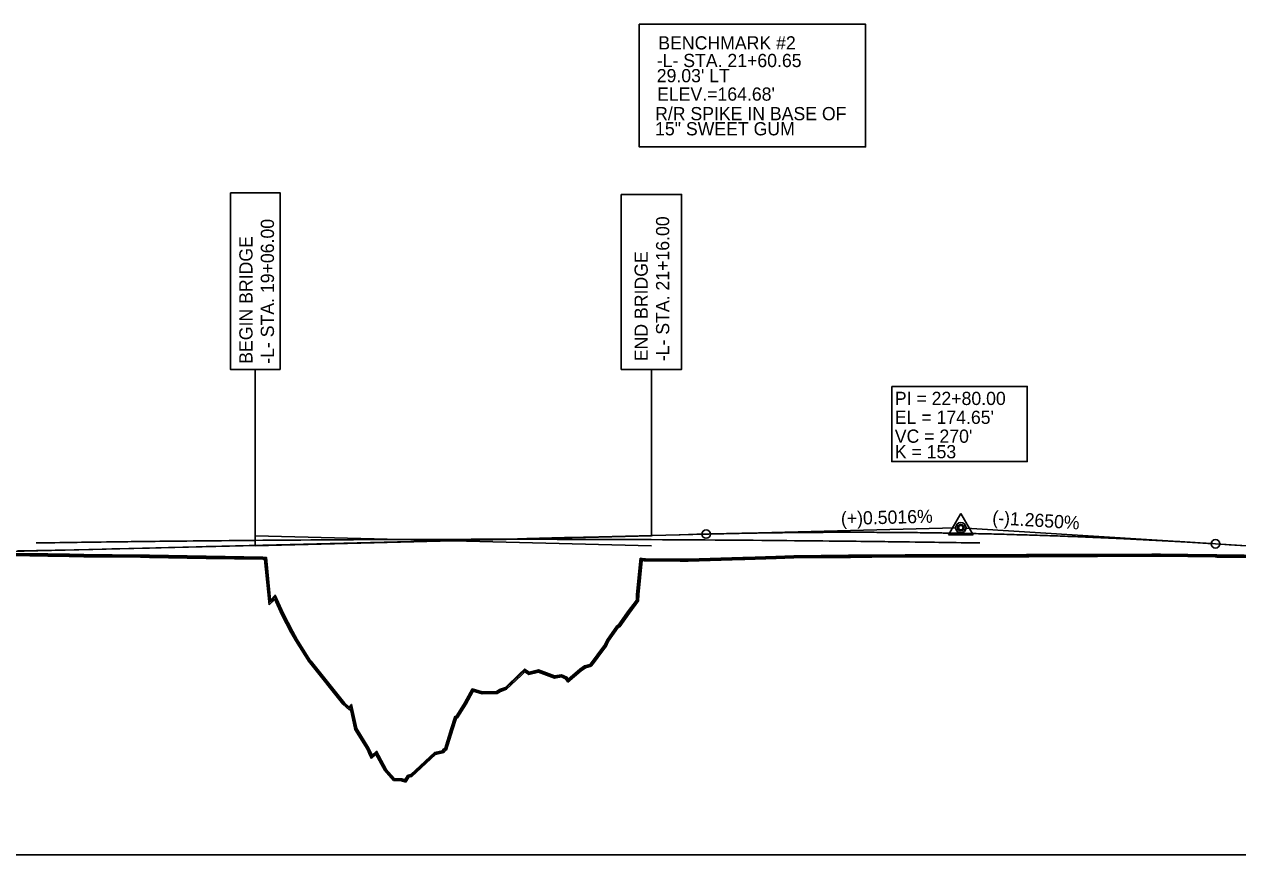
# Model space of a CAD drawing. Extents: x 2321227 to 2323611, y 920570 to 921870.
# Drawn here: x 2322011 to 2322654, y 920570 to 921010 of the extents above; entities that cross this region are included whole.
import ezdxf

# ---------------------------------------------------------------- set-up
doc = ezdxf.new("R2010")
doc.units = 0
for name, color, linetype in [('Exist Profile Cell', 7, 'Continuous'), ('Exist Vertical Profile Ground Line', 7, 'Continuous'), ('Prop Grid Mask', 7, 'Continuous'), ('Prop PFL Text', 7, 'Continuous'), ('Prop PFL VPI Symbol CELL', 7, 'Continuous'), ('Prop Vertical Profile Curve Label', 7, 'Continuous'), ('Prop Vertical Profile Grade', 7, 'Continuous'), ('Prop Vertical Profile Grade Label', 7, 'Continuous'), ('Prop VPI Label', 7, 'Continuous'), ('Scratch_Level_0', 7, 'Continuous'), ('Scratch_Level_1', 7, 'Continuous'), ('Scratch_Level_2', 7, 'Continuous'), ('Scratch_Level_3', 7, 'Continuous'), ('Scratch_Level_5', 7, 'Continuous')]:
    doc.layers.add(name, color=color, linetype=linetype)

# ---------------------------------------------------------------- blocks, each defined once
blk = doc.blocks.new('Profile VPI Symbol')
at = {"layer": 'Prop PFL VPI Symbol CELL'}
for p, q in [((-0.001, 0.147), (-0.13, -0.077)), ((-0.001, 0.147), (0.129, -0.077)), ((-0.13, -0.077), (0.129, -0.077))]:
    blk.add_line(p, q, dxfattribs=at)
for radius in [0.035, 0.024]:
    blk.add_circle((-0.001, -0.003), radius, dxfattribs=at)

msp = doc.modelspace()

# ---------------------------------------------------------------- linework, layer by layer
at = {"layer": 'Exist Profile Cell'}
msp.add_line((2321226.97, 920570.07), (2323610.74, 920570.07), dxfattribs=at)
at = {"layer": 'Exist Vertical Profile Ground Line'}
for p, q in [((2322003.77, 920728.54), (2322022.98, 920728.33)), ((2322022.98, 920728.33), (2322033.77, 920728.21)), ((2322033.77, 920728.21), (2322034.12, 920728.23)), ((2322034.12, 920728.23), (2322034.57, 920728.02)), ((2322034.57, 920728.02), (2322042.1, 920727.95)), ((2322042.1, 920727.95), (2322072.1, 920727.7)), ((2322512.97, 920727.93), (2322541.79, 920727.96)), ((2322541.79, 920727.96), (2322542.99, 920727.97)), ((2322542.99, 920727.97), (2322549, 920727.98)), ((2322549, 920727.98), (2322549.41, 920727.98)), ((2322549.41, 920727.98), (2322561.55, 920728.02)), ((2322561.55, 920728.02), (2322578.22, 920728.08)), ((2322578.22, 920728.08), (2322579.39, 920728.08)), ((2322579.39, 920728.08), (2322608.29, 920728.19)), ((2322608.29, 920728.19), (2322609.37, 920728.19)), ((2322609.37, 920728.19), (2322612.4, 920728.2)), ((2322612.4, 920728.2), (2322612.79, 920728.2)), ((2322612.79, 920728.2), (2322641.81, 920727.82)), ((2322072.1, 920727.7), (2322076.92, 920727.61)), ((2322076.92, 920727.61), (2322106.93, 920727.09)), ((2322106.93, 920727.09), (2322136.96, 920726.57)), ((2322136.96, 920726.57), (2322137.87, 920726.54)), ((2322137.87, 920726.54), (2322140.31, 920702.47)), ((2322336.24, 920707.89), (2322338.03, 920725.88)), ((2322338.03, 920725.88), (2322339.15, 920725.74)), ((2322339.15, 920725.74), (2322339.83, 920725.74)), ((2322339.83, 920725.74), (2322358.16, 920725.55)), ((2322358.16, 920725.55), (2322361.73, 920725.52)), ((2322361.73, 920725.52), (2322362.42, 920725.55)), ((2322362.42, 920725.55), (2322391.54, 920726.48)), ((2322391.54, 920726.48), (2322392.5, 920726.52)), ((2322392.5, 920726.52), (2322409.01, 920727.05)), ((2322409.01, 920727.05), (2322418.43, 920727.35)), ((2322418.43, 920727.35), (2322447.47, 920727.59)), ((2322447.47, 920727.59), (2322448.41, 920727.6)), ((2322448.41, 920727.6), (2322459.86, 920727.69)), ((2322459.86, 920727.69), (2322477.56, 920727.84)), ((2322477.56, 920727.84), (2322478.39, 920727.85)), ((2322478.39, 920727.85), (2322482.95, 920727.89)), ((2322482.95, 920727.89), (2322510.7, 920727.91)), ((2322510.7, 920727.91), (2322511.96, 920727.92)), ((2322511.96, 920727.92), (2322512.97, 920727.93)), ((2322641.81, 920727.82), (2322642.71, 920727.79)), ((2322642.71, 920727.79), (2322663.25, 920727.52)), ((2322140.31, 920702.47), (2322141.87, 920704.12)), ((2322141.87, 920704.12), (2322143.21, 920705.63)), ((2322143.21, 920705.63), (2322146.99, 920697.31)), ((2322331.27, 920698.07), (2322336.14, 920704.63)), ((2322336.14, 920704.63), (2322336.24, 920707.89)), ((2322146.99, 920697.31), (2322151.91, 920687.84)), ((2322326.15, 920690.77), (2322331.27, 920698.07)), ((2322320.31, 920683.21), (2322325.37, 920690.43)), ((2322325.37, 920690.43), (2322326.15, 920690.77)), ((2322151.91, 920687.84), (2322154.24, 920683.56)), ((2322154.24, 920683.56), (2322161.52, 920672)), ((2322318.92, 920680.3), (2322320.31, 920683.21)), ((2322312.08, 920671.18), (2322317.63, 920678.64)), ((2322317.63, 920678.64), (2322318.92, 920680.3)), ((2322161.52, 920672), (2322161.91, 920671.78)), ((2322161.91, 920671.78), (2322179.5, 920649.78)), ((2322311.01, 920669.91), (2322312.08, 920671.18)), ((2322266.19, 920657.73), (2322273.89, 920665.03)), ((2322273.89, 920665.03), (2322275.9, 920667.03)), ((2322275.9, 920667.03), (2322278.04, 920665.51)), ((2322278.04, 920665.51), (2322283.09, 920666.81)), ((2322283.09, 920666.81), (2322291.59, 920663.62)), ((2322291.59, 920663.62), (2322295.24, 920664.3)), ((2322295.24, 920664.3), (2322297.44, 920663.24)), ((2322298.73, 920661.54), (2322305.78, 920667.44)), ((2322305.78, 920667.44), (2322307.99, 920669.14)), ((2322307.99, 920669.14), (2322311.01, 920669.91)), ((2322262.91, 920656.62), (2322266.19, 920657.73)), ((2322297.44, 920663.24), (2322298.73, 920661.54)), ((2322244.83, 920649.91), (2322248.57, 920656.64)), ((2322248.57, 920656.64), (2322253.21, 920655.25)), ((2322253.21, 920655.25), (2322261.22, 920655.53)), ((2322261.22, 920655.53), (2322262.91, 920656.62)), ((2322179.5, 920649.78), (2322182.96, 920646.58)), ((2322182.96, 920646.58), (2322183.47, 920647.21)), ((2322183.47, 920647.21), (2322185.77, 920636.48)), ((2322240.12, 920642.52), (2322244.83, 920649.91)), ((2322237.78, 920636.5), (2322239.65, 920642.42)), ((2322239.65, 920642.42), (2322240.12, 920642.52)), ((2322185.77, 920636.48), (2322192.29, 920626.04)), ((2322234.31, 920625.66), (2322237.78, 920636.5)), ((2322192.29, 920626.04), (2322193.77, 920622.59)), ((2322232.88, 920624.21), (2322233.43, 920625.18)), ((2322233.43, 920625.18), (2322234.31, 920625.66)), ((2322193.77, 920622.59), (2322194.69, 920621.12)), ((2322194.69, 920621.12), (2322196.97, 920623.11)), ((2322196.97, 920623.11), (2322201.41, 920614.81)), ((2322216.06, 920611.5), (2322228.56, 920623.17)), ((2322228.56, 920623.17), (2322232.88, 920624.21)), ((2322201.41, 920614.81), (2322206.31, 920609.37)), ((2322206.31, 920609.37), (2322210.53, 920609.16)), ((2322210.53, 920609.16), (2322212.79, 920608.51)), ((2322212.79, 920608.51), (2322214.44, 920611.14)), ((2322214.44, 920611.14), (2322216.06, 920611.5))]:
    msp.add_line(p, q, dxfattribs=at)
at = {"layer": 'Prop Grid Mask'}
for points in [[(2322336.52, 921010.03), (2322456.52, 921010.03), (2322456.52, 920945.03), (2322336.52, 920945.03)], [(2322119.82, 920920.74), (2322146.12, 920920.74), (2322146.12, 920827.2), (2322119.82, 920827.2)], [(2322326.96, 920919.86), (2322358.98, 920919.86), (2322358.98, 920827.2), (2322326.96, 920827.2)], [(2322470.38, 920818.15), (2322542.17, 920818.15), (2322542.17, 920778.32), (2322470.38, 920778.32)]]:
    msp.add_lwpolyline(points, close=True, dxfattribs=at)
at = {"layer": 'Prop Vertical Profile Curve Label'}
for p, q in [((2322132.97, 920733.94), (2322132.97, 920827.2)), ((2322342.97, 920739.21), (2322342.97, 920827.2))]:
    msp.add_line(p, q, dxfattribs=at)
for centre in [(2322371.97, 920739.94), (2322641.97, 920734.79)]:
    msp.add_circle(centre, 2.25, dxfattribs=at)
at = {"layer": 'Prop Vertical Profile Grade'}
for p, q in [((2322001.97, 920730.66), (2322371.97, 920739.94)), ((2322641.97, 920734.79), (2322666.97, 920733.2))]:
    msp.add_line(p, q, dxfattribs=at)
msp.add_spline([(2322371.97, 920739.94), (2322377.37, 920740.07), (2322382.77, 920740.19), (2322388.17, 920740.3), (2322393.57, 920740.4), (2322398.97, 920740.5), (2322404.37, 920740.58), (2322409.77, 920740.65), (2322415.17, 920740.72), (2322420.57, 920740.77), (2322425.97, 920740.82), (2322431.37, 920740.85), (2322436.77, 920740.88), (2322442.17, 920740.89), (2322447.57, 920740.9), (2322452.97, 920740.9), (2322458.37, 920740.88), (2322463.77, 920740.86), (2322469.17, 920740.83), (2322474.57, 920740.79), (2322479.97, 920740.74), (2322485.37, 920740.68), (2322490.77, 920740.61), (2322496.17, 920740.53), (2322501.57, 920740.44), (2322506.97, 920740.34), (2322512.37, 920740.24), (2322517.77, 920740.12), (2322523.17, 920739.99), (2322528.57, 920739.85), (2322533.97, 920739.71), (2322539.37, 920739.55), (2322544.77, 920739.39), (2322550.17, 920739.21), (2322555.57, 920739.03), (2322560.97, 920738.84), (2322566.37, 920738.63), (2322571.77, 920738.42), (2322577.17, 920738.2), (2322582.57, 920737.97), (2322587.97, 920737.72), (2322593.37, 920737.47), (2322598.77, 920737.21), (2322604.17, 920736.94), (2322609.57, 920736.66), (2322614.97, 920736.37), (2322620.37, 920736.08), (2322625.77, 920735.77), (2322631.17, 920735.45), (2322636.57, 920735.12), (2322641.97, 920734.79)], degree=3, dxfattribs=at)
at = {"layer": 'Prop VPI Label'}
for p, q in [((2322371.97, 920739.94), (2322504.22, 920743.26)), ((2322641.97, 920734.79), (2322509.72, 920743.15))]:
    msp.add_line(p, q, dxfattribs=at)
msp.add_circle((2322506.97, 920743.32), 2.75, dxfattribs=at)
at = {"layer": 'Scratch_Level_0'}
msp.add_open_spline([(2322016.91, 920735.23), (2322027.32, 920735.39), (2322037.74, 920735.54), (2322058.58, 920735.82), (2322089.84, 920736.21), (2322162.77, 920736.91), (2322266.97, 920737.31), (2322371.17, 920736.91), (2322444.1, 920736.21), (2322475.36, 920735.82), (2322496.2, 920735.54), (2322506.62, 920735.39), (2322517.03, 920735.23)], degree=3, dxfattribs=at)
at = {"layer": 'Scratch_Level_1'}
for p, q in [((2322132.97, 920738.97), (2322342.97, 920733.72)), ((2322342.97, 920738.97), (2322132.97, 920733.72))]:
    msp.add_line(p, q, dxfattribs=at)
for points in [[(2321985.27, 920729.85), (2322023, 920729.43), (2322033.74, 920729.31), (2322034.33, 920729.35), (2322034.82, 920729.12), (2322042.11, 920729.05), (2322072.11, 920728.8), (2322076.94, 920728.71), (2322106.95, 920728.19), (2322136.99, 920727.67), (2322138.87, 920727.6), (2322141.16, 920704.98), (2322143.51, 920707.62), (2322147.98, 920697.79), (2322152.88, 920688.36), (2322155.19, 920684.12), (2322162.29, 920672.83), (2322162.63, 920672.64), (2322180.31, 920650.53), (2322182.85, 920648.18), (2322184.06, 920649.68), (2322186.81, 920636.9), (2322193.27, 920626.55), (2322194.75, 920623.1), (2322194.94, 920622.8), (2322197.28, 920624.85), (2322202.32, 920615.45), (2322206.82, 920610.45), (2322210.71, 920610.26), (2322212.3, 920609.8), (2322213.75, 920612.11), (2322215.53, 920612.51), (2322228.02, 920624.17), (2322232.16, 920625.17), (2322232.62, 920625.99), (2322233.4, 920626.42), (2322236.73, 920636.83), (2322238.8, 920643.37), (2322239.45, 920643.5), (2322243.89, 920650.48), (2322248.04, 920657.95), (2322253.35, 920656.36), (2322260.88, 920656.62), (2322262.43, 920657.62), (2322265.61, 920658.7), (2322273.12, 920665.82), (2322275.78, 920668.46), (2322278.26, 920666.71), (2322283.16, 920667.96), (2322291.69, 920664.76), (2322295.39, 920665.45), (2322298.15, 920664.11), (2322298.91, 920663.12), (2322305.09, 920668.29), (2322307.5, 920670.15), (2322310.39, 920670.89), (2322311.22, 920671.87), (2322316.76, 920679.31), (2322317.98, 920680.88), (2322319.36, 920683.77), (2322324.65, 920691.32), (2322325.43, 920691.66), (2322330.38, 920698.72), (2322335.05, 920705.01), (2322335.15, 920707.96), (2322337.05, 920727.12), (2322339.22, 920726.84), (2322339.83, 920726.84), (2322358.18, 920726.65), (2322361.71, 920726.62), (2322362.38, 920726.65), (2322391.5, 920727.58), (2322392.46, 920727.62), (2322408.98, 920728.15), (2322418.41, 920728.45), (2322447.46, 920728.69), (2322448.4, 920728.7), (2322477.55, 920728.94), (2322478.37, 920728.95), (2322482.95, 920728.99), (2322511.96, 920729.02), (2322512.97, 920729.03), (2322541.78, 920729.06), (2322542.98, 920729.07), (2322549, 920729.08), (2322549.4, 920729.08), (2322578.22, 920729.18), (2322579.38, 920729.18), (2322608.29, 920729.29), (2322609.37, 920729.29), (2322612.79, 920729.3), (2322641.83, 920728.92), (2322642.74, 920728.89), (2322671.88, 920728.51)], [(2321985.27, 920729.37), (2322022.99, 920728.96), (2322033.76, 920728.83), (2322034.24, 920728.87), (2322034.71, 920728.64), (2322042.11, 920728.57), (2322072.11, 920728.32), (2322076.93, 920728.24), (2322106.94, 920727.72), (2322136.98, 920727.2), (2322138.44, 920727.14), (2322140.8, 920703.9), (2322141.41, 920704.55), (2322143.38, 920706.76), (2322147.55, 920697.58), (2322152.47, 920688.14), (2322154.78, 920683.88), (2322161.96, 920672.47), (2322162.32, 920672.27), (2322179.96, 920650.21), (2322182.89, 920647.49), (2322183.81, 920648.61), (2322186.36, 920636.72), (2322192.84, 920626.33), (2322194.33, 920622.88), (2322194.83, 920622.08), (2322197.15, 920624.1), (2322201.93, 920615.17), (2322206.6, 920609.99), (2322210.64, 920609.78), (2322212.51, 920609.24), (2322214.05, 920611.69), (2322215.76, 920612.08), (2322228.25, 920623.74), (2322232.47, 920624.76), (2322232.97, 920625.64), (2322233.79, 920626.09), (2322237.18, 920636.69), (2322239.17, 920642.96), (2322239.74, 920643.08), (2322244.29, 920650.23), (2322248.27, 920657.38), (2322253.29, 920655.88), (2322261.02, 920656.15), (2322262.64, 920657.19), (2322265.86, 920658.28), (2322273.45, 920665.48), (2322275.83, 920667.84), (2322278.17, 920666.19), (2322283.13, 920667.46), (2322291.65, 920664.27), (2322295.32, 920664.95), (2322297.85, 920663.74), (2322298.83, 920662.44), (2322305.39, 920667.92), (2322307.71, 920669.71), (2322310.66, 920670.47), (2322311.59, 920671.57), (2322317.14, 920679.02), (2322318.39, 920680.63), (2322319.77, 920683.53), (2322324.96, 920690.94), (2322325.74, 920691.27), (2322330.76, 920698.44), (2322335.52, 920704.84), (2322335.62, 920707.93), (2322337.48, 920726.59), (2322339.19, 920726.36), (2322339.83, 920726.36), (2322358.17, 920726.18), (2322361.72, 920726.14), (2322362.4, 920726.17), (2322391.51, 920727.11), (2322392.48, 920727.14), (2322408.99, 920727.68), (2322418.42, 920727.97), (2322447.47, 920728.21), (2322448.41, 920728.23), (2322477.56, 920728.46), (2322478.38, 920728.47), (2322482.95, 920728.51), (2322511.96, 920728.54), (2322512.97, 920728.55), (2322541.78, 920728.58), (2322542.99, 920728.59), (2322549, 920728.6), (2322549.4, 920728.6), (2322578.22, 920728.7), (2322579.39, 920728.71), (2322608.29, 920728.81), (2322609.37, 920728.81), (2322612.79, 920728.82), (2322641.82, 920728.44), (2322642.73, 920728.41), (2322671.87, 920728.03)]]:
    msp.add_lwpolyline(points, dxfattribs=at)
at = {"layer": 'Scratch_Level_2'}
msp.add_lwpolyline([(2322006.97, 920731), (2322016.97, 920731.2), (2322026.97, 920731.42), (2322036.97, 920731.63), (2322046.97, 920731.86), (2322056.97, 920732.08), (2322066.97, 920732.32), (2322076.97, 920732.56), (2322086.97, 920732.8), (2322096.97, 920733.05), (2322102.96, 920733.2), (2322102.97, 920733.2), (2322106.97, 920733.3), (2322107.97, 920733.33), (2322136.97, 920734.06), (2322146.97, 920734.31), (2322166.97, 920734.81), (2322186.97, 920735.31), (2322216.97, 920736.06), (2322236.97, 920736.56), (2322256.97, 920737.06), (2322266.97, 920737.31), (2322276.97, 920737.56), (2322296.97, 920738.06), (2322316.97, 920738.56), (2322342.97, 920739.22), (2322357.97, 920739.59), (2322358.16, 920739.6), (2322366.97, 920739.82), (2322367.97, 920739.84), (2322372.96, 920739.97), (2322372.97, 920739.97), (2322372.98, 920739.97), (2322373.97, 920739.99), (2322374.97, 920740.02), (2322376.97, 920740.06), (2322386.97, 920740.28), (2322396.97, 920740.47), (2322406.97, 920740.62), (2322416.97, 920740.74), (2322426.97, 920740.83), (2322436.97, 920740.88), (2322446.97, 920740.9), (2322456.97, 920740.89), (2322466.97, 920740.85), (2322476.97, 920740.77), (2322486.97, 920740.66), (2322496.97, 920740.52), (2322506.97, 920740.34), (2322516.97, 920740.14), (2322526.97, 920739.9), (2322536.97, 920739.62), (2322546.97, 920739.32), (2322556.97, 920738.98), (2322566.97, 920738.61), (2322576.97, 920738.21), (2322576.98, 920738.21), (2322581.47, 920738.01), (2322581.97, 920737.99), (2322586.47, 920737.79), (2322586.72, 920737.78), (2322586.97, 920737.77), (2322596.97, 920737.3), (2322606.97, 920736.8), (2322616.97, 920736.26), (2322626.97, 920735.7), (2322626.98, 920735.7), (2322636.97, 920735.1), (2322646.97, 920734.47), (2322649.22, 920734.33), (2322666.97, 920733.2)], dxfattribs=at)
at = {"layer": 'Scratch_Level_3'}
for p in [(2322132.97, 920780.58), (2322342.97, 920738.97)]:
    msp.add_line(p, (2322132.97, 920733.72), dxfattribs=at)
at = {"layer": 'Scratch_Level_5'}
for p, q in [((2322342.97, 920738.97), (2322132.97, 920733.72)), ((2321874.34, 920727.48), (2322133.83, 920733.98))]:
    msp.add_line(p, q, dxfattribs=at)

# ---------------------------------------------------------------- block references
at = {"layer": 'Prop Grid Mask', "xscale": 50, "yscale": 50}
msp.add_blockref('Profile VPI Symbol', (2322507.01, 920743.46), dxfattribs=at)

# ---------------------------------------------------------------- texts
at = {"layer": 'Prop PFL Text'}
for s, p in [('BENCHMARK #2', (2322346.64, 920996.67)), ('-L- STA. 21+60.65', (2322345.8, 920987.34)), ("29.03' LT", (2322345.8, 920979.32)), ("ELEV.=164.68'", (2322345.98, 920969.55)), ('R/R SPIKE IN BASE OF', (2322344.92, 920959.19)), ('15" SWEET GUM', (2322344.92, 920951.17))]:
    msp.add_text(s, height=7, rotation=360, dxfattribs=at).set_placement(p)
at = {"layer": 'Prop Vertical Profile Curve Label'}
for s, p in [("VC = 270'", (2322471.97, 920788.32)), ('K = 153', (2322471.97, 920780.09))]:
    msp.add_text(s, height=7, dxfattribs=at).set_placement(p)
at = {"layer": 'Prop Vertical Profile Grade Label'}
for s, rotation, p in [('(+)0.5016%', 1.43671, (2322443.5, 920744.73)), ('(-)1.2650%', 356.38086, (2322523.49, 920745.29))]:
    msp.add_text(s, height=7, rotation=rotation, dxfattribs=at).set_placement(p)
at = {"layer": 'Prop VPI Label'}
for s, p in [('-L- STA. 19+06.00', (2322142.93, 920830.17)), ('-L- STA. 21+16.00', (2322352.41, 920831.52)), ('BEGIN BRIDGE', (2322131.55, 920830.17)), ('END BRIDGE', (2322341.03, 920831.52))]:
    msp.add_text(s, height=7, rotation=90, dxfattribs=at).set_placement(p)
for s, p in [('PI = 22+80.00', (2322471.97, 920808.32)), ("EL = 174.65'", (2322471.97, 920798.32))]:
    msp.add_text(s, height=7, dxfattribs=at).set_placement(p)

doc.saveas('drawing.dxf')
